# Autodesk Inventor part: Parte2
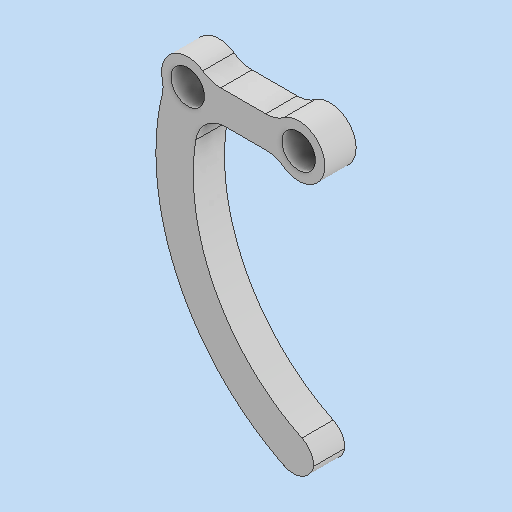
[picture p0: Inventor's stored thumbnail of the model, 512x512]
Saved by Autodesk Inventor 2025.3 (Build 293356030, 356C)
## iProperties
Created: 2026-05
Part Number: Parte2
Material: Generico
Document SubType Name: Modeling
Designer: Ryzen5700u
Density: 1 g/cm^3
Appearance: Default
Author: Ryzen5700u
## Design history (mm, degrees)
sketch "Schizzo1"
  geometry: L1 (0, 0)-(-12, 0); L2 (1.431, 0)-(1.431, -29.515); L3 (0, -3)-(-9.277, -3); L4 (2.155, -25.973)-(2.155, 0); L5 (1.431, -29.515)-(1.431, -25.693); L6 (0, 0)-(0, -3); L7 (-12, 0)-(-9.277, -3); C1 r 2.5 at (0, -1.5); C2 r 2.5 at (-10.638, -1.5); A1 r 22.185 centre (8.498, -8.486) between (-12, 0) and (1.431, -29.515); A2 r 18.602 centre (8.498, -8.486) between (-9.277, -3) and (1.431, -25.693); 4 further points
  constraints: 14 end point, 5 point on circle, 4 centre point, 2 midpoint, 2 point on line, 2 vertical, 1 horizontal
  dimensions: "d0" = 12 distance of L1.start L1.end; "d1" = 3 distance between parallel lines of L1 L3; "d2" = 5 diameter of C1; "d3" = 5 diameter of C2
extrude "Estrusione1" new body sketch "Schizzo1" distance "d4" = 3; taper "d5" = 0 deg
sketch "Schizzo2"
  geometry: A1 r 2.5 centre (0, -1.5) between (-2, -3) and (-2, 0) reference; A2 r 2.5 centre (-10.638, -1.5) between (-8.638, 0) and (-12.889, -2.589) reference; 3 further points
  constraints: 2 coincident
hole "Foro1" sketch "Schizzo2" at (0, -1.5), (-10.638, -1.5) diameter "d6" = 3.2; stored, may be unused: countersink angle "d10" = 90 deg, drill point angle "d12" = 118 deg; dims "d7" = 5, "d8" = 4, "d9" = 2, "d11" = 8
fillet "Raccordo1" dims "d13" = 3
fillet "Raccordo2" dims "d14" = 2
fillet "Raccordo3" dims "d15" = 3
node "Solido1"
